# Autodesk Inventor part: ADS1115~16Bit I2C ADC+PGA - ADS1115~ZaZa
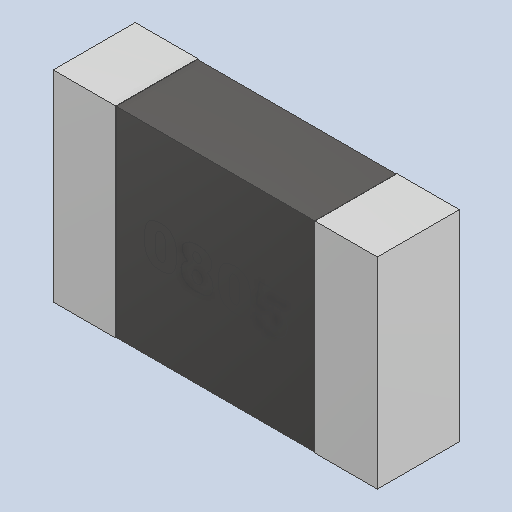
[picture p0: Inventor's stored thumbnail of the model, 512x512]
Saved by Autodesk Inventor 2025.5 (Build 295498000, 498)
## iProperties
Created: 2026-10
Part Number: ADS1115~16Bit I2C ADC+PGA - ADS1115~ZaZa
Material: Genérico
Description: 0805 Inductor
Document SubType Name: Modeling
Designer: Luis M
Density: 1 g/cm^3
Appearance: Valor por defecto
Author: Luis M
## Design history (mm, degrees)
feature "Base1"
node "Sólido1"
